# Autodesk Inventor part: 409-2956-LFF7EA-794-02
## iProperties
Created: 2010-11
Part Number: 409-2956-LFF7EA-794-02
Cost Center: 0 lbmass
Material: A304 STAINLESS STEEL
Document SubType Name: Sheet Metal
Designer: S. Boerckel
Authority: 0 in^3
Mass: 794.445 g
Surface Area: 357.51 cm^2
Volume: 98.3224 cm^3
Density: 8.08 g/cm^3
Flat Pattern Width: 5.08 cm
Flat Pattern Length: 35.56 cm
Flat Pattern Area: 180.645 cm^2
Sheet Metal Rule: 1/4"Thk
Description: 2" PIPE ANGLE SUPPORT
User Status: SHEAR
SaveDate: 2008-01-15
SaveTime: 10:24
FileName: Sheet Metal
Wide: =<Flat Pattern Width>cm
Length: =<Flat Pattern Length>cm
Thickness: 0.2500 in
SMR: =<Sheet Metal Rule> - <Material>
Author: S. Boerckel
Revision Number: 0
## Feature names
1. Plate1
